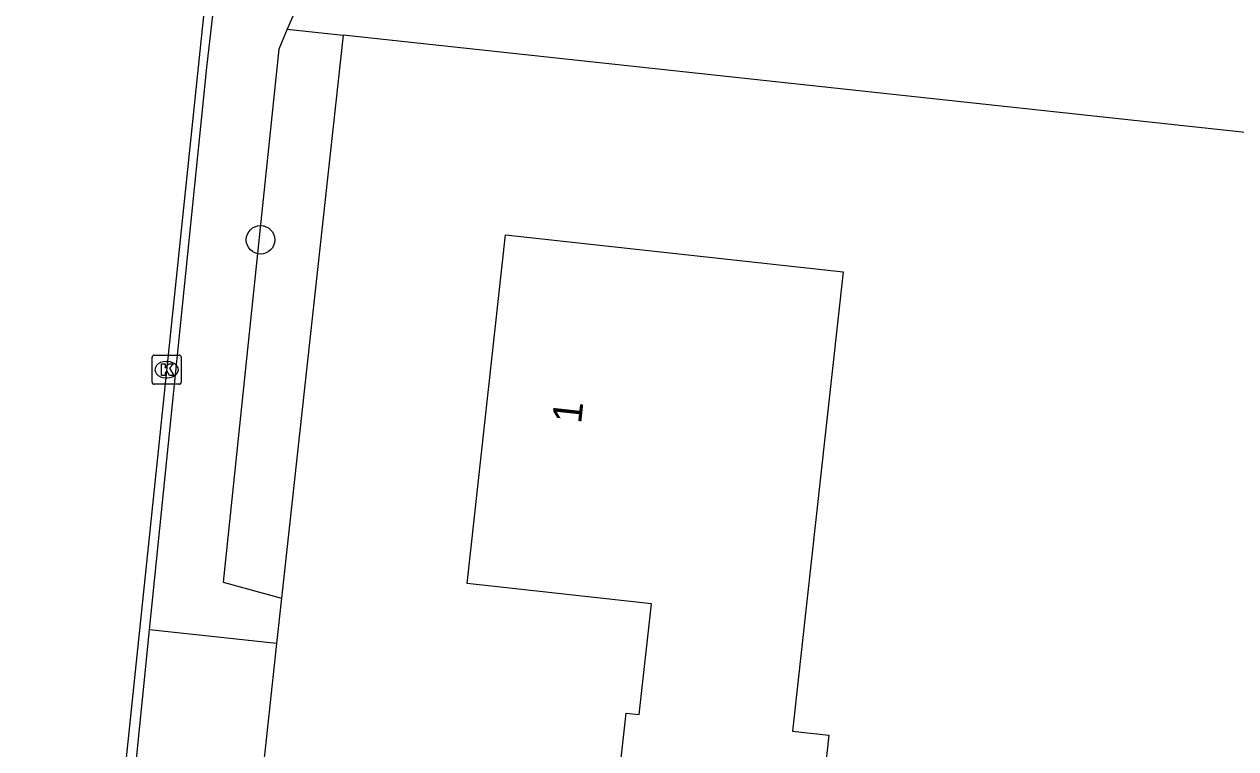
# Model space of a CAD drawing. Extents: x 162157 to 163165, y 378998 to 380775.
# Drawn here: x 162295.27 to 162336.77, y 380586.58 to 380611.42 of the extents above; entities that cross this region are included whole.
import ezdxf

# ---------------------------------------------------------------- set-up
doc = ezdxf.new("R2010")
doc.units = 0
for name, color, linetype in [('IMGEO_Boom', 7, 'Continuous'), ('IMGEO_Groenvoorziening', 7, 'Continuous'), ('IMGEO_Kolk', 7, 'Continuous'), ('IMGEO_Pand', 7, 'Continuous'), ('IMGEO_Pand_nummerreeks', 7, 'Continuous'), ('IMGEO_Rijbaan_lokaal_gesloten', 7, 'Continuous'), ('IMGEO_Rijbaan_lokaal_open', 7, 'Continuous'), ('IMGEO_Voetpad_open', 7, 'Continuous')]:
    doc.layers.add(name, color=color, linetype=linetype)

msp = doc.modelspace()

# ---------------------------------------------------------------- linework, layer by layer
at = {"layer": 'IMGEO_Boom'}
msp.add_circle((162303.361, 380604.03), 0.489, dxfattribs=at)
at = {"layer": 'IMGEO_Groenvoorziening'}
for points in [[(162318.483, 380626.064), (162305.138, 380612.567), (162304.556, 380611.905), (162304.277, 380611.251)], [(162338.841, 380624.519), (162337.095, 380607.712), (162306.19, 380611.044)], [(162304.277, 380611.251), (162303.987, 380610.571), (162302.083, 380592.294), (162304.083, 380591.744)], [(162306.19, 380611.044), (162304.083, 380591.744)], [(162304.277, 380611.251), (162306.19, 380611.044)], [(162304.083, 380591.744), (162303.914, 380590.185)]]:
    msp.add_lwpolyline(points, dxfattribs=at)
at = {"layer": 'IMGEO_Kolk'}
for p, q in [((162299.646, 380599.15), (162299.646, 380600.002)), ((162299.721, 380600.076), (162300.573, 380600.076)), ((162300.134, 380599.856), (162300.159, 380599.856)), ((162300.647, 380600.002), (162300.647, 380599.15)), ((162300.573, 380599.076), (162299.721, 380599.076)), ((162300.157, 380599.296), (162300.132, 380599.296))]:
    msp.add_line(p, q, dxfattribs=at)
for points in [[(162299.646, 380599.15), (162299.646, 380600.002)], [(162299.721, 380600.076), (162300.573, 380600.076)], [(162299.967, 380599.776), (162300.09, 380599.776), (162300.09, 380599.625), (162300.22, 380599.776), (162300.384, 380599.776), (162300.238, 380599.625), (162300.391, 380599.376), (162300.239, 380599.376), (162300.154, 380599.54), (162300.09, 380599.473), (162300.09, 380599.376), (162299.967, 380599.376), (162299.967, 380599.776)], [(162300.647, 380600.002), (162300.647, 380599.15)], [(162300.573, 380599.076), (162299.721, 380599.076)]]:
    msp.add_lwpolyline(points, dxfattribs=at)
for centre, start, end in [((162299.723, 380600), 91.552, 178.448), ((162299.723, 380600), 91.552, 178.448), ((162300.571, 380600), 1.552, 88.448), ((162300.571, 380600), 1.552, 88.448), ((162299.723, 380599.152), 181.552, 268.448), ((162299.723, 380599.152), 181.552, 268.448), ((162300.571, 380599.152), 271.552, 358.448), ((162300.571, 380599.152), 271.552, 358.448)]:
    msp.add_arc(centre, 0.0765, start, end, dxfattribs=at)
for centre, major_axis, ratio, start_param, end_param in [((162300.133, 380599.576), (-0.387, 0.002), 0.722429, 4.712389, 7.853982), ((162300.158, 380599.576), (-0.39, 0.002), 0.717154, 1.570796, 4.712389)]:
    msp.add_ellipse(centre, major_axis=major_axis, ratio=ratio, start_param=start_param, end_param=end_param, dxfattribs=at)
at = {"layer": 'IMGEO_Pand'}
msp.add_lwpolyline([(162315.421, 380583.574), (162315.887, 380587.806), (162316.336, 380587.757), (162316.753, 380591.553), (162310.441, 380592.247), (162311.756, 380604.202), (162323.321, 380602.93), (162322.774, 380597.961), (162322.718, 380597.452), (162321.587, 380587.179), (162322.831, 380587.042), (162322.371, 380582.864)], dxfattribs=at)
at = {"layer": 'IMGEO_Rijbaan_lokaal_gesloten'}
msp.add_lwpolyline([(162302.301, 380620.086), (162302.073, 380618.08), (162298.145, 380580.349), (162293.721, 380538.975), (162292.56, 380528.03)], dxfattribs=at)
at = {"layer": 'IMGEO_Rijbaan_lokaal_open'}
for points in [[(162299.562, 380590.653), (162301.518, 380609.937), (162302.695, 380620.164)], [(162298.645, 380581.609), (162299.32, 380588.269), (162299.562, 380590.653)]]:
    msp.add_lwpolyline(points, dxfattribs=at)
at = {"layer": 'IMGEO_Voetpad_open'}
for points in [[(162303.914, 380590.185), (162299.562, 380590.653)], [(162303.914, 380590.185), (162303.648, 380587.741), (162302.936, 380581.196)]]:
    msp.add_lwpolyline(points, dxfattribs=at)

# ---------------------------------------------------------------- texts
at = {"layer": 'IMGEO_Pand_nummerreeks'}
msp.add_text('1', height=1, rotation=83.7229, dxfattribs=at).set_placement((162314.341, 380597.705))

doc.saveas('drawing.dxf')
